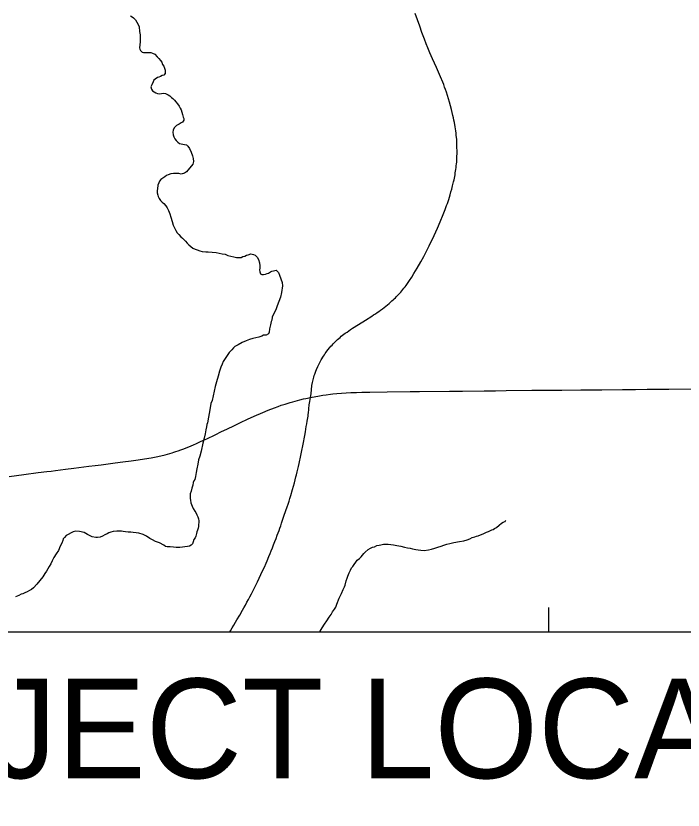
# Model space of a CAD drawing. Extents: x 0 to 34, y 0 to 22.
# Drawn here: x 6.666 to 7.603, y 17.323 to 18.439 of the extents above; entities that cross this region are included whole.
import ezdxf

# ---------------------------------------------------------------- set-up
doc = ezdxf.new("R2010")
doc.units = 0
for name, color, linetype in [('GM_X_City_Street', 7, 'Continuous'), ('GM_X_County_Road', 7, 'Continuous'), ('GM_X_Minor_River', 7, 'Continuous'), ('SH_Text', 7, 'Continuous')]:
    doc.layers.add(name, color=color, linetype=linetype)

msp = doc.modelspace()

# ---------------------------------------------------------------- linework, layer by layer
at = {"layer": 'GM_X_City_Street'}
for points in [[(6.9663, 17.574), (6.9671, 17.5754), (6.9695, 17.5794), (6.9719, 17.5835), (6.9742, 17.5877), (6.9762, 17.591), (6.9801, 17.5976), (6.9839, 17.6043), (6.9858, 17.6077), (6.988, 17.6115), (6.9902, 17.6154), (6.9924, 17.6193), (6.9945, 17.6233), (6.9966, 17.6272), (7.0051, 17.6442), (7.0075, 17.6494), (7.0099, 17.6545), (7.0123, 17.6597), (7.0147, 17.665), (7.0171, 17.6704), (7.0186, 17.6739), (7.0211, 17.6799), (7.0228, 17.6839), (7.0244, 17.6879), (7.026, 17.692), (7.0277, 17.6964), (7.0294, 17.7008), (7.0311, 17.7053), (7.0328, 17.7097), (7.0341, 17.7131), (7.0354, 17.7164), (7.0366, 17.7198), (7.0378, 17.7231), (7.039, 17.7265), (7.0428, 17.7378), (7.0467, 17.7494), (7.048, 17.7534), (7.0494, 17.7574), (7.0506, 17.7614), (7.0518, 17.7654), (7.0543, 17.774), (7.0556, 17.7785), (7.0569, 17.7831), (7.0581, 17.7876), (7.0591, 17.7915), (7.0599, 17.7947), (7.0608, 17.7986), (7.0618, 17.8025), (7.0627, 17.8064), (7.0635, 17.8104), (7.066, 17.8217), (7.0669, 17.8262), (7.0691, 17.8374), (7.0715, 17.8496), (7.0724, 17.8549), (7.0731, 17.8586), (7.0737, 17.8624), (7.0744, 17.8661), (7.075, 17.8698), (7.0754, 17.8722), (7.0758, 17.8746), (7.0761, 17.8769), (7.0764, 17.8793), (7.0767, 17.8817), (7.0773, 17.8865), (7.0774, 17.8875), (7.0778, 17.8927), (7.0785, 17.8976), (7.0794, 17.9033), (7.0805, 17.9085), (7.0815, 17.92), (7.0823, 17.9245), (7.0831, 17.9278), (7.0843, 17.932), (7.0849, 17.934), (7.0856, 17.9361), (7.0872, 17.9404), (7.0881, 17.9425), (7.0899, 17.9468), (7.0909, 17.9488), (7.0928, 17.9526), (7.0947, 17.9562), (7.098, 17.9615), (7.0991, 17.9633), (7.1003, 17.965), (7.1016, 17.9668), (7.1041, 17.9701), (7.1069, 17.9735), (7.1083, 17.9752), (7.1098, 17.9768), (7.1113, 17.9785), (7.1128, 17.9801), (7.1144, 17.9816), (7.116, 17.9832), (7.1177, 17.9847), (7.1194, 17.9862), (7.1211, 17.9877), (7.1229, 17.9892), (7.1247, 17.9906), (7.1266, 17.9921), (7.1284, 17.9934), (7.1309, 17.9952), (7.1334, 17.997), (7.136, 17.9987), (7.1385, 18.0004), (7.1411, 18.0021), (7.1568, 18.012), (7.1657, 18.0175), (7.1683, 18.0192), (7.1708, 18.0208), (7.1732, 18.0225), (7.1757, 18.0242), (7.1781, 18.026), (7.1806, 18.0278), (7.183, 18.0296), (7.1853, 18.0315), (7.1877, 18.0334), (7.19, 18.0354), (7.194, 18.0388), (7.1956, 18.0403), (7.1972, 18.0418), (7.1988, 18.0433), (7.2004, 18.0449), (7.2019, 18.0464), (7.2034, 18.048), (7.2064, 18.0514), (7.208, 18.0532), (7.2095, 18.055), (7.2109, 18.0569), (7.2124, 18.0587), (7.2138, 18.0606), (7.2186, 18.0674), (7.2219, 18.0723), (7.225, 18.0773), (7.2296, 18.0851), (7.2345, 18.0937), (7.2387, 18.1013), (7.2465, 18.1161), (7.2535, 18.1306), (7.2581, 18.1409), (7.2619, 18.1501), (7.266, 18.1601), (7.2687, 18.1672), (7.2698, 18.17), (7.2709, 18.1728), (7.2719, 18.1756), (7.2729, 18.1785), (7.2738, 18.1814), (7.2759, 18.1881), (7.277, 18.1921), (7.2781, 18.196), (7.2793, 18.2006), (7.2807, 18.2063), (7.2813, 18.2088), (7.2818, 18.2113), (7.2823, 18.2137), (7.2827, 18.2162), (7.2831, 18.2187), (7.2838, 18.2237), (7.2842, 18.2262), (7.2845, 18.2288), (7.2848, 18.2313), (7.285, 18.2339), (7.2852, 18.2364), (7.2854, 18.2423), (7.2855, 18.2456), (7.2854, 18.2589), (7.2852, 18.2622), (7.285, 18.2656), (7.2844, 18.2719), (7.2841, 18.2748), (7.2837, 18.2778), (7.2833, 18.2807), (7.2829, 18.2837), (7.2818, 18.2898), (7.2812, 18.293), (7.2805, 18.2962), (7.2798, 18.2993), (7.2778, 18.3077), (7.2765, 18.3129), (7.2751, 18.3182), (7.2737, 18.3229), (7.2722, 18.3276), (7.2707, 18.3323), (7.2694, 18.3358), (7.2681, 18.3393), (7.2668, 18.3428), (7.2654, 18.3463), (7.2623, 18.3536), (7.2594, 18.3602), (7.2565, 18.3668), (7.2539, 18.3728), (7.251, 18.3792), (7.2475, 18.3877), (7.2445, 18.3944), (7.2422, 18.4), (7.2397, 18.4065), (7.2361, 18.4161), (7.233, 18.4248), (7.2299, 18.4338), (7.2268, 18.4429)], [(7.4142, 17.6083), (7.4141, 17.5914), (7.4139, 17.574)]]:
    msp.add_lwpolyline(points, dxfattribs=at)
at = {"layer": 'GM_X_County_Road'}
msp.add_lwpolyline([(6.6562, 17.7923), (6.6767, 17.795), (6.697, 17.7976), (6.7088, 17.799), (6.7152, 17.7999), (6.7214, 17.8007), (6.7282, 17.8014), (6.7351, 17.8023), (6.7471, 17.8039), (6.7682, 17.8067), (6.7768, 17.8078), (6.7853, 17.8088), (6.8051, 17.8114), (6.8157, 17.8127), (6.8275, 17.8141), (6.8374, 17.8154), (6.8464, 17.8168), (6.8558, 17.8184), (6.8625, 17.8196), (6.8694, 17.8211), (6.8753, 17.8225), (6.8818, 17.8244), (6.8853, 17.8255), (6.8877, 17.8263), (6.8901, 17.8271), (6.8938, 17.8284), (6.8973, 17.8296), (6.9002, 17.8307), (6.9088, 17.834), (6.9152, 17.8369), (6.9192, 17.8386), (6.9241, 17.8409), (6.929, 17.8431), (6.9339, 17.8453), (6.9454, 17.8509), (6.9547, 17.8552), (6.9618, 17.8587), (6.9729, 17.8639), (6.9813, 17.868), (6.9912, 17.8728), (7.0005, 17.877), (7.0124, 17.8822), (7.0199, 17.8853), (7.0288, 17.8887), (7.0341, 17.8907), (7.0382, 17.8922), (7.0441, 17.894), (7.0511, 17.8962), (7.0549, 17.8972), (7.0648, 17.9), (7.0698, 17.9012), (7.0731, 17.902), (7.0794, 17.9033), (7.0922, 17.9056), (7.0967, 17.9063), (7.1014, 17.907), (7.1076, 17.9078), (7.1111, 17.9082), (7.1168, 17.9089), (7.1233, 17.9093), (7.1297, 17.9097), (7.1362, 17.9101), (7.1444, 17.9104), (7.1519, 17.9106), (7.1629, 17.9108), (7.1873, 17.9113), (7.2197, 17.9115), (7.2327, 17.9116), (7.2751, 17.9119), (7.2934, 17.9122), (7.3238, 17.9126), (7.3394, 17.9128), (7.3545, 17.913), (7.3906, 17.9133), (7.4327, 17.9135), (7.4593, 17.9138), (7.4888, 17.9141), (7.5182, 17.9144), (7.5364, 17.9146), (7.5528, 17.9147), (7.5831, 17.9151), (7.6163, 17.9155)], dxfattribs=at)
at = {"layer": 'GM_X_Minor_River'}
for points in [[(6.8267, 18.4396), (6.829, 18.4381), (6.8309, 18.4365)], [(6.8309, 18.4365), (6.8336, 18.4339), (6.8375, 18.4275), (6.8386, 18.424), (6.8394, 18.4176), (6.8403, 18.4126), (6.8403, 18.4077), (6.84, 18.4031), (6.8396, 18.3985), (6.8393, 18.3947), (6.8397, 18.3925), (6.8405, 18.3906), (6.8428, 18.3883), (6.8447, 18.3879), (6.8469, 18.3879), (6.8504, 18.388), (6.853, 18.388), (6.8553, 18.388), (6.8576, 18.3872), (6.8606, 18.3857), (6.8641, 18.382), (6.8664, 18.3793), (6.8687, 18.3767), (6.8706, 18.3744), (6.8718, 18.371), (6.8733, 18.3687), (6.8745, 18.366), (6.8753, 18.363), (6.8753, 18.3603), (6.8753, 18.3584), (6.8735, 18.3561), (6.8712, 18.3554), (6.8689, 18.3542), (6.8666, 18.3534), (6.8644, 18.3527), (6.8613, 18.3507), (6.8595, 18.3492), (6.8583, 18.3465), (6.8568, 18.3427), (6.8554, 18.3397), (6.8561, 18.3362), (6.8577, 18.3343), (6.86, 18.3325), (6.8623, 18.3313), (6.8646, 18.3302), (6.8676, 18.3298), (6.8729, 18.331), (6.8756, 18.3303), (6.8794, 18.3284), (6.8817, 18.3269), (6.8844, 18.3246), (6.8863, 18.3231), (6.8886, 18.3208), (6.8905, 18.3186), (6.8928, 18.3156), (6.8948, 18.3125), (6.8963, 18.3099), (6.8979, 18.3072), (6.8986, 18.3042), (6.8998, 18.3008), (6.9006, 18.2973), (6.9014, 18.2951), (6.9014, 18.2928), (6.8995, 18.2901), (6.8976, 18.2889), (6.895, 18.2874), (6.8931, 18.2862), (6.8912, 18.2855), (6.8878, 18.282), (6.8867, 18.279), (6.886, 18.2759), (6.8864, 18.2721), (6.8875, 18.2695), (6.8891, 18.2668), (6.8906, 18.2645), (6.8929, 18.2619), (6.8956, 18.26), (6.8979, 18.2596), (6.9002, 18.2593), (6.9025, 18.2589), (6.9051, 18.2582), (6.9071, 18.2563), (6.9097, 18.2532), (6.9121, 18.2479), (6.9136, 18.2426), (6.9148, 18.2388), (6.9152, 18.2346), (6.9141, 18.2312), (6.9051, 18.2201), (6.9024, 18.2182), (6.8979, 18.217), (6.8945, 18.2178), (6.891, 18.2181), (6.8869, 18.2181), (6.8831, 18.2173), (6.8797, 18.2161), (6.877, 18.215), (6.8747, 18.2134), (6.8721, 18.2115), (6.8694, 18.2096), (6.8676, 18.2073)], [(6.8676, 18.2073), (6.8664, 18.2046), (6.865, 18.2016), (6.8646, 18.1966), (6.8643, 18.194), (6.8643, 18.1909), (6.8651, 18.1875), (6.8655, 18.1856), (6.867, 18.1826), (6.8689, 18.1799), (6.8712, 18.1776), (6.8735, 18.1757), (6.8762, 18.1727), (6.8782, 18.1697), (6.8801, 18.1659), (6.882, 18.1613), (6.8832, 18.1564), (6.8852, 18.1503), (6.8867, 18.1454), (6.8883, 18.1416), (6.8902, 18.1378), (6.8922, 18.1344), (6.8945, 18.1321), (6.8972, 18.1291), (6.8998, 18.1272), (6.9021, 18.1249), (6.9041, 18.1227), (6.9064, 18.12), (6.9087, 18.1177), (6.9113, 18.1155), (6.9144, 18.1132), (6.9175, 18.1117), (6.9205, 18.1106), (6.924, 18.1095), (6.9274, 18.1084), (6.9327, 18.108), (6.9358, 18.1077), (6.9472, 18.107), (6.9514, 18.1062), (6.9556, 18.1051), (6.9597, 18.1044), (6.9636, 18.1029), (6.9678, 18.1018), (6.9719, 18.101), (6.9758, 18.0999), (6.9799, 18.1), (6.9822, 18.1), (6.9845, 18.1011), (6.9871, 18.1019), (6.9898, 18.1031), (6.9921, 18.1038), (6.9955, 18.105), (6.9974, 18.1046), (6.9997, 18.1043), (7.002, 18.1031), (7.0046, 18.1005), (7.0066, 18.0971), (7.0081, 18.0925), (7.0086, 18.088), (7.0082, 18.0849), (7.0078, 18.0826), (7.0086, 18.0796), (7.0094, 18.0769), (7.0113, 18.0762), (7.0136, 18.0758), (7.0163, 18.0766), (7.0185, 18.0774), (7.0204, 18.0781), (7.0235, 18.0797), (7.0254, 18.0805), (7.0276, 18.0812), (7.0314, 18.082), (7.0345, 18.079), (7.0361, 18.0752), (7.038, 18.0699), (7.0396, 18.0646), (7.04, 18.06), (7.0389, 18.0509), (7.0375, 18.0444), (7.0349, 18.0379), (7.0326, 18.0318), (7.0308, 18.0265), (7.0282, 18.0211), (7.0259, 18.0162), (7.0252, 18.012), (7.0245, 18.0101), (7.0234, 18.0055), (7.0219, 17.9998), (7.0216, 17.9952), (7.0204, 17.9925), (7.0174, 17.991), (7.0155, 17.991), (7.0136, 17.9906), (7.011, 17.9894), (7.0068, 17.9882), (7.0026, 17.9871), (6.9984, 17.9859), (6.9939, 17.9847), (6.989, 17.9828), (6.9837, 17.9805), (6.978, 17.9774)], [(6.978, 17.9774), (6.9734, 17.9747), (6.9712, 17.9728), (6.9689, 17.9701), (6.9655, 17.9663), (6.9614, 17.9609), (6.9588, 17.9567), (6.9569, 17.9537), (6.9554, 17.9502), (6.9536, 17.9456), (6.9517, 17.9403), (6.9499, 17.9331), (6.9477, 17.9251), (6.9458, 17.9186), (6.9443, 17.9121), (6.9429, 17.9056), (6.9414, 17.8991), (6.9396, 17.8949), (6.9385, 17.8888), (6.9349, 17.8675), (6.9341, 17.8652), (6.9334, 17.8622), (6.9327, 17.8576), (6.9316, 17.8523), (6.9301, 17.8462), (6.9283, 17.8389), (6.9257, 17.8279), (6.9239, 17.821), (6.9224, 17.8157), (6.9213, 17.8096), (6.9198, 17.8031), (6.9187, 17.7977), (6.918, 17.792), (6.9169, 17.7878), (6.9158, 17.7859), (6.9147, 17.7836), (6.9143, 17.7798), (6.9129, 17.7756), (6.9118, 17.7718), (6.9106, 17.768), (6.9103, 17.7646), (6.9103, 17.7615), (6.9107, 17.7589), (6.9115, 17.7551), (6.9131, 17.7505), (6.9146, 17.7471), (6.9169, 17.7437), (6.9185, 17.7414), (6.92, 17.7384), (6.9212, 17.7357), (6.9224, 17.7327), (6.9228, 17.73), (6.9228, 17.7274), (6.9224, 17.7247), (6.9221, 17.722), (6.9217, 17.7194), (6.9206, 17.7167), (6.9199, 17.7144), (6.9195, 17.7121), (6.9184, 17.7083), (6.9173, 17.706), (6.9158, 17.7037), (6.9147, 17.7003), (6.9136, 17.6976), (6.9117, 17.6957), (6.9094, 17.6945), (6.9067, 17.6938), (6.8961, 17.6926), (6.8908, 17.6925), (6.887, 17.6929), (6.8824, 17.6932), (6.8782, 17.6936), (6.8759, 17.6939), (6.8736, 17.6958), (6.8675, 17.6988), (6.8618, 17.7011), (6.8576, 17.703), (6.8538, 17.7052), (6.8492, 17.7082), (6.8442, 17.7109), (6.8385, 17.7127), (6.8347, 17.7131), (6.8305, 17.7134), (6.8271, 17.7138), (6.8233, 17.7141), (6.8195, 17.7145), (6.8161, 17.7149), (6.8141, 17.7152), (6.8115, 17.7156), (6.8073, 17.7152), (6.8024, 17.7148), (6.7989, 17.714), (6.7963, 17.7132), (6.794, 17.7117), (6.7906, 17.7101), (6.7872, 17.7082), (6.7838, 17.707), (6.7804, 17.7063), (6.7777, 17.7066), (6.7728, 17.7073), (6.7697, 17.7088)], [(7.0922, 17.574), (7.093, 17.5751), (7.096, 17.5797), (7.0994, 17.5847), (7.1024, 17.5896), (7.1057, 17.5946), (7.1084, 17.5984), (7.1106, 17.6019), (7.1132, 17.6057), (7.1151, 17.6088), (7.1166, 17.613), (7.12, 17.6213), (7.1233, 17.6278), (7.1256, 17.6332), (7.1274, 17.6374), (7.1282, 17.6397), (7.1296, 17.6458), (7.1311, 17.6492), (7.1322, 17.6523), (7.1337, 17.6568), (7.136, 17.6607), (7.1374, 17.6637), (7.139, 17.6656), (7.1453, 17.6748), (7.1484, 17.6771), (7.1506, 17.6794), (7.1525, 17.6817), (7.1544, 17.684), (7.1563, 17.6859), (7.1608, 17.6897), (7.1638, 17.6913), (7.1668, 17.6928), (7.1695, 17.6936), (7.1729, 17.6951), (7.1759, 17.6959), (7.1782, 17.6963), (7.182, 17.6971), (7.1839, 17.6971), (7.1858, 17.6971), (7.1889, 17.6972), (7.1923, 17.6968), (7.1961, 17.6964), (7.2007, 17.6953), (7.2064, 17.6942), (7.2117, 17.6931), (7.2159, 17.692), (7.2197, 17.6913), (7.2228, 17.6905), (7.2254, 17.6902), (7.2277, 17.6898), (7.2311, 17.6891), (7.2346, 17.6887), (7.2395, 17.6884), (7.2452, 17.6892), (7.2498, 17.6899), (7.2543, 17.6915), (7.2585, 17.6927), (7.263, 17.6942), (7.2668, 17.6958), (7.271, 17.6973), (7.2756, 17.6981), (7.2812, 17.6997), (7.2892, 17.7009), (7.2949, 17.702), (7.2998, 17.7032), (7.3033, 17.7048), (7.307, 17.7063), (7.3105, 17.7075), (7.3127, 17.7083), (7.3154, 17.709), (7.3233, 17.7121), (7.3271, 17.7141), (7.3298, 17.7148), (7.3343, 17.7171), (7.3362, 17.7179), (7.3381, 17.7191), (7.3408, 17.7206), (7.3445, 17.7237), (7.3479, 17.7264), (7.3502, 17.7279), (7.3525, 17.7291), (7.3532, 17.7291), (7.354, 17.731)], [(6.7697, 17.7088), (6.7663, 17.7107), (6.764, 17.7122), (6.7617, 17.7134), (6.7548, 17.7148), (6.7499, 17.7152), (6.7461, 17.7144), (6.7362, 17.7094), (6.734, 17.7067), (6.7321, 17.7044), (6.7314, 17.7021), (6.7299, 17.6983), (6.728, 17.6941), (6.7254, 17.6884), (6.722, 17.6834), (6.719, 17.6784), (6.7164, 17.6739), (6.7145, 17.6693), (6.7123, 17.6658), (6.7104, 17.6624), (6.7086, 17.6593), (6.7063, 17.6559), (6.7033, 17.6513), (6.6992, 17.646), (6.695, 17.641), (6.6901, 17.6356), (6.6875, 17.6333), (6.6845, 17.6318), (6.6814, 17.6302), (6.678, 17.6287), (6.6754, 17.6275), (6.6731, 17.6268), (6.6697, 17.6252), (6.6651, 17.6233)]]:
    msp.add_lwpolyline(points, dxfattribs=at)
at = {"layer": 'SH_Text'}
msp.add_lwpolyline([(6.1606, 17.574), (8.2521, 17.574), (8.2521, 17.0741), (6.1606, 17.0741)], close=True, dxfattribs=at)

# ---------------------------------------------------------------- texts
msp.add_text('PROJECT LOCATION', height=0.14, dxfattribs=at).set_placement((6.2239, 17.3683))

doc.saveas('drawing.dxf')
